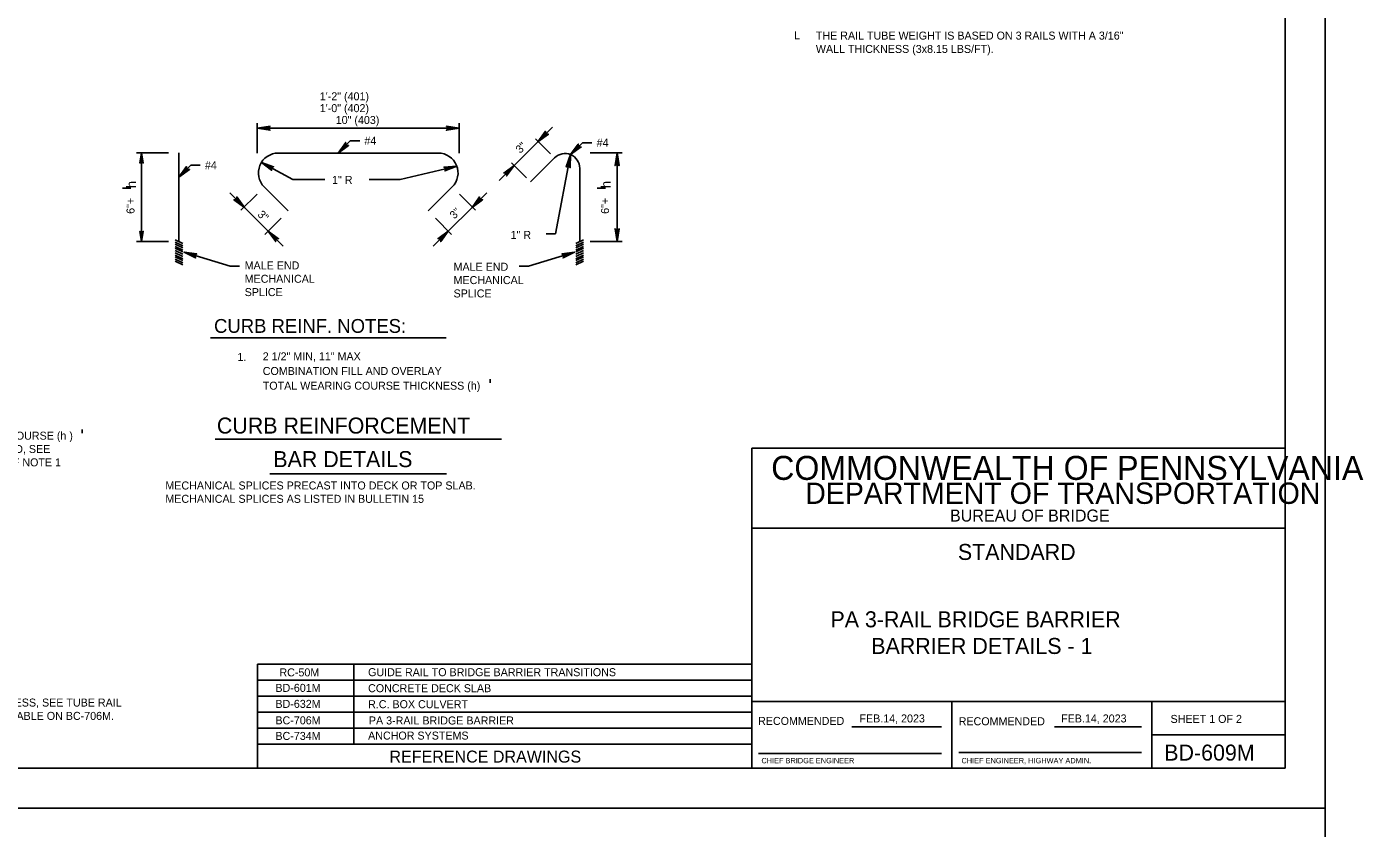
# Model space of a CAD drawing. Extents: x 641054 to 641910, y 298137 to 299325.
# Drawn here: x 641409 to 641910, y 298724 to 299024 of the extents above; entities that cross this region are included whole.
import ezdxf

# ---------------------------------------------------------------- set-up
doc = ezdxf.new("R2010")
doc.units = 0
for name, color, linetype in [('1', 7, 'Continuous'), ('2', 7, 'Continuous'), ('4', 7, 'Continuous'), ('DATES', 7, 'Continuous'), ('PLT-BNDY', 7, 'Continuous'), ('SIGNATORY TITLES', 7, 'Continuous')]:
    doc.layers.add(name, color=color, linetype=linetype)

msp = doc.modelspace()

# ---------------------------------------------------------------- linework, layer by layer
at = {"layer": '1'}
for p, q in [((641467.09, 298939.97), (641464.27, 298941.33)), ((641467.09, 298939.09), (641464.27, 298940.46)), ((641467.09, 298943.18), (641464.28, 298944.55)), ((641467.09, 298942.31), (641464.28, 298943.68)), ((641467.09, 298941.56), (641464.28, 298942.92)), ((641467.09, 298940.68), (641464.28, 298942.04)), ((641614.55, 298943.18), (641617.36, 298944.55)), ((641614.55, 298942.31), (641617.36, 298943.68)), ((641614.55, 298941.56), (641617.36, 298942.92)), ((641614.55, 298940.68), (641617.36, 298942.04)), ((641614.55, 298939.97), (641617.37, 298941.33)), ((641614.55, 298939.09), (641617.37, 298940.46)), ((641467.09, 298938.3), (641464.27, 298939.66)), ((641467.09, 298937.43), (641464.27, 298938.79)), ((641467.09, 298935.84), (641464.27, 298937.21)), ((641467.09, 298936.71), (641464.28, 298938.08)), ((641467.09, 298935.08), (641464.28, 298936.45)), ((641484.85, 298934.68), (641467.59, 298939.85)), ((641596.79, 298934.68), (641614.05, 298939.85)), ((641614.55, 298938.3), (641617.37, 298939.66)), ((641614.55, 298937.43), (641617.37, 298938.79)), ((641614.55, 298936.71), (641617.36, 298938.08)), ((641614.55, 298935.84), (641617.37, 298937.21)), ((641614.55, 298935.08), (641617.36, 298936.45)), ((641582.43, 298890.84), (641582.43, 298892.25))]:
    msp.add_line(p, q, dxfattribs=at)
for points in [[(641499.61, 298985.77), (641499.44, 298986.1), (641495.06, 298986.34), (641499.61, 298985.77), (641499.84, 298985.57), (641495.06, 298986.34), (641499.43, 298986.55), (641499.59, 298986.88), (641495.06, 298986.34), (641499.84, 298987.1), (641499.59, 298986.88)], [(641566.21, 298986.91), (641566.38, 298986.58), (641570.75, 298986.34), (641566.21, 298986.91), (641565.98, 298987.11), (641570.75, 298986.34), (641566.38, 298986.12), (641566.22, 298985.8), (641570.75, 298986.34), (641565.98, 298985.58), (641566.22, 298985.8)], [(641603.9, 298984.1), (641603.55, 298984.21), (641600.29, 298981.29), (641603.9, 298984.1), (641604.21, 298984.12), (641600.29, 298981.29), (641603.22, 298984.53), (641603.11, 298984.87), (641600.29, 298981.29), (641603.13, 298985.2), (641603.11, 298984.87)], [(641630.54, 298972.56), (641630.21, 298972.73), (641629.97, 298977.1), (641630.54, 298972.56), (641630.74, 298972.32), (641629.97, 298977.1), (641629.75, 298972.73), (641629.43, 298972.57), (641629.97, 298977.1), (641629.21, 298972.32), (641629.43, 298972.57)], [(641500.34, 298970.87), (641500.34, 298971.24), (641496.61, 298973.53), (641500.34, 298970.87), (641500.45, 298970.58), (641496.61, 298973.53), (641500.56, 298971.64), (641500.85, 298971.85), (641496.61, 298973.53), (641501.17, 298971.93), (641500.85, 298971.85)], [(641565.33, 298971.66), (641565.57, 298971.38), (641569.88, 298972.15), (641565.33, 298971.66), (641565.06, 298971.8), (641569.88, 298972.15), (641565.68, 298970.94), (641565.6, 298970.58), (641569.88, 298972.15), (641565.41, 298970.32), (641565.6, 298970.58)], [(641587.77, 298969.58), (641588.12, 298969.46), (641591.38, 298972.38), (641587.77, 298969.58), (641587.47, 298969.55), (641591.38, 298972.38), (641588.45, 298969.14), (641588.57, 298968.8), (641591.38, 298972.38), (641588.55, 298968.47), (641588.57, 298968.8)], [(641486.61, 298959.49), (641486.97, 298959.6), (641490.23, 298956.68), (641486.61, 298959.49), (641486.31, 298959.51), (641490.23, 298956.68), (641487.29, 298959.92), (641487.41, 298960.26), (641490.23, 298956.68), (641487.39, 298960.59), (641487.41, 298960.26)], [(641579.2, 298959.49), (641578.85, 298959.6), (641575.59, 298956.68), (641579.2, 298959.49), (641579.51, 298959.51), (641575.59, 298956.68), (641578.52, 298959.92), (641578.41, 298960.26), (641575.59, 298956.68), (641578.43, 298960.59), (641578.41, 298960.26)], [(641502.74, 298944.97), (641502.39, 298944.86), (641499.13, 298947.78), (641502.74, 298944.97), (641503.05, 298944.94), (641499.13, 298947.78), (641502.07, 298944.53), (641501.95, 298944.19), (641499.13, 298947.78), (641501.97, 298943.86), (641501.95, 298944.19)], [(641563.07, 298944.97), (641563.42, 298944.86), (641566.68, 298947.78), (641563.07, 298944.97), (641562.77, 298944.94), (641566.68, 298947.78), (641563.75, 298944.53), (641563.87, 298944.19), (641566.68, 298947.78), (641563.85, 298943.86), (641563.87, 298944.19)], [(641630.54, 298948.4), (641630.21, 298948.23), (641629.97, 298943.86), (641630.54, 298948.4), (641630.74, 298948.64), (641629.97, 298943.86), (641629.75, 298948.23), (641629.43, 298948.39), (641629.97, 298943.86), (641629.21, 298948.64), (641629.43, 298948.39)], [(641472.1, 298939.09), (641471.84, 298938.83), (641467.59, 298939.85), (641472.1, 298939.09), (641472.38, 298939.22), (641467.59, 298939.85), (641471.71, 298938.39), (641471.77, 298938.03), (641467.59, 298939.85), (641471.94, 298937.75), (641471.77, 298938.03)], [(641609.54, 298939.09), (641609.8, 298938.83), (641614.05, 298939.85), (641609.54, 298939.09), (641609.26, 298939.22), (641614.05, 298939.85), (641609.93, 298938.39), (641609.87, 298938.03), (641614.05, 298939.85), (641609.7, 298937.75), (641609.87, 298938.03)]]:
    msp.add_lwpolyline(points, dxfattribs=at)
at = {"layer": '2'}
for p, q in [((641880.49, 299310.38), (641880.49, 298746.38)), ((641495.06, 298977.03), (641495.06, 298988.26)), ((641570.75, 298986.34), (641495.06, 298986.34)), ((641570.75, 298977.03), (641570.75, 298988.26)), ((641600.29, 298981.29), (641605.78, 298986.78)), ((641525.34, 298977.03), (641529.95, 298981.64)), ((641533.46, 298981.64), (641529.95, 298981.64)), ((641591.38, 298972.38), (641600.29, 298981.29)), ((641599.42, 298982.36), (641604.98, 298976.81)), ((641612.55, 298976.44), (641617.04, 298980.93)), ((641620.55, 298980.93), (641617.04, 298980.93)), ((641449.78, 298977.07), (641461.74, 298977.07)), ((641606.9, 298946.8), (641612.55, 298976.44)), ((641631.86, 298977.07), (641619.9, 298977.07)), ((641465.69, 298968), (641470.18, 298972.49)), ((641473.69, 298972.49), (641470.18, 298972.49)), ((641496.61, 298973.53), (641508.43, 298967.14)), ((641548.61, 298967.14), (641569.88, 298972.15)), ((641585.7, 298966.7), (641591.38, 298972.38)), ((641590.41, 298973.36), (641595.97, 298967.8)), ((641520.4, 298967.14), (641508.43, 298967.14)), ((641537.01, 298967.14), (641548.61, 298967.14)), ((641444.52, 298963.9), (641447.67, 298963.9)), ((641490.23, 298956.68), (641484.73, 298962.18)), ((641494.97, 298961.63), (641488.91, 298955.57)), ((641570.84, 298961.63), (641576.9, 298955.57)), ((641575.59, 298956.68), (641581.08, 298962.18)), ((641622.44, 298963.9), (641625.58, 298963.9)), ((641499.13, 298947.78), (641490.23, 298956.68)), ((641566.68, 298947.78), (641575.59, 298956.68)), ((641503.98, 298952.63), (641497.92, 298946.56)), ((641561.83, 298952.63), (641567.9, 298946.56)), ((641504.82, 298942.09), (641499.13, 298947.78)), ((641561, 298942.09), (641566.68, 298947.78)), ((641606.9, 298946.8), (641603.39, 298946.8)), ((641449.78, 298943.86), (641461.74, 298943.86)), ((641631.86, 298943.86), (641619.9, 298943.86)), ((641488.36, 298934.68), (641484.85, 298934.68)), ((641596.79, 298934.68), (641593.28, 298934.68)), ((641477.54, 298907.79), (641565.84, 298907.79)), ((641429.35, 298871.98), (641429.35, 298873.37)), ((641479.24, 298869.79), (641586.58, 298869.79)), ((641880.49, 298866.38), (641680.49, 298866.38)), ((641680.49, 298866.38), (641680.49, 298746.38)), ((641880.49, 298746.38), (641880.49, 298866.38)), ((641499.81, 298856.78), (641566.01, 298856.78)), ((641880.49, 298836.38), (641680.49, 298836.38)), ((641495.11, 298785.38), (641495.11, 298746.38)), ((641495.11, 298785.38), (641680.49, 298785.38)), ((641531.24, 298785.38), (641531.24, 298755.38)), ((641495.11, 298779.38), (641680.49, 298779.38)), ((641495.11, 298773.38), (641680.49, 298773.38)), ((641880.49, 298771.38), (641680.49, 298771.38)), ((641755.49, 298746.38), (641755.49, 298771.38)), ((641830.49, 298771.38), (641830.49, 298746.38)), ((641495.11, 298767.38), (641680.49, 298767.38)), ((641495.11, 298761.38), (641680.49, 298761.38)), ((641717.94, 298761.88), (641751.63, 298761.88)), ((641793.93, 298761.88), (641826.54, 298761.88)), ((641495.11, 298755.38), (641680.49, 298755.38)), ((641830.49, 298758.88), (641880.49, 298758.88)), ((641682.99, 298751.88), (641751.63, 298751.88)), ((641758.11, 298752.25), (641826.54, 298752.25)), ((641094.49, 298746.38), (641880.49, 298746.38))]:
    msp.add_line(p, q, dxfattribs=at)
for points in [[(641529.01, 298979.89), (641528.65, 298980), (641525.34, 298977.03), (641529.01, 298979.89), (641529.32, 298979.91), (641525.34, 298977.03), (641528.32, 298980.33), (641528.2, 298980.67), (641525.34, 298977.03), (641528.22, 298981.01), (641528.2, 298980.67)], [(641616.22, 298979.29), (641615.86, 298979.41), (641612.55, 298976.44), (641616.22, 298979.29), (641616.53, 298979.32), (641612.55, 298976.44), (641615.53, 298979.73), (641615.41, 298980.08), (641612.55, 298976.44), (641615.43, 298980.41), (641615.41, 298980.08)], [(641451.21, 298973.46), (641451.48, 298973.6), (641451.67, 298977.1), (641451.21, 298973.46), (641451.05, 298973.28), (641451.67, 298977.1), (641451.84, 298973.6), (641452.1, 298973.47), (641451.67, 298977.1), (641452.28, 298973.28), (641452.1, 298973.47)], [(641451.67, 298943.86), (641451.67, 298977.07)], [(641611.12, 298972.02), (641611.48, 298972.12), (641612.55, 298976.44), (641611.12, 298972.02), (641610.88, 298971.82), (641612.55, 298976.44), (641611.94, 298972.04), (641612.23, 298971.82), (641612.55, 298976.44), (641612.4, 298971.53), (641612.23, 298971.82)], [(641629.97, 298943.86), (641629.97, 298977.07)], [(641469.36, 298970.85), (641469, 298970.97), (641465.69, 298968), (641469.36, 298970.85), (641469.67, 298970.88), (641465.69, 298968), (641468.67, 298971.29), (641468.55, 298971.64), (641465.69, 298968), (641468.57, 298971.97), (641468.55, 298971.64)], [(641451.21, 298947.5), (641451.48, 298947.36), (641451.67, 298943.86), (641451.21, 298947.5), (641451.05, 298947.68), (641451.67, 298943.86), (641451.84, 298947.36), (641452.1, 298947.49), (641451.67, 298943.86), (641452.28, 298947.68), (641452.1, 298947.49)]]:
    msp.add_lwpolyline(points, dxfattribs=at)
at = {"layer": '4'}
for p, q in [((641465.69, 298977.07), (641465.69, 298943.86)), ((641562.89, 298977.03), (641502.93, 298977.03)), ((641597.53, 298966.24), (641606.54, 298975.24)), ((641615.95, 298971.35), (641615.95, 298943.86)), ((641506.67, 298955.32), (641497.66, 298964.32)), ((641559.14, 298955.32), (641568.15, 298964.32))]:
    msp.add_line(p, q, dxfattribs=at)
for centre, radius, start, end in [((641502.93, 298969.59), 7.44, 90, 225), ((641562.89, 298969.59), 7.44, 315, 90), ((641610.44, 298971.35), 5.51, 360, 135)]:
    msp.add_arc(centre, radius, start, end, dxfattribs=at)
at = {"layer": 'PLT-BNDY'}
for points in [[(641054.49, 299325.38), (641895.49, 299325.38), (641895.49, 298731.38), (641054.49, 298731.38)], [(641054.49, 298731.38), (641895.49, 298731.38), (641895.49, 298137.38), (641054.49, 298137.38)]]:
    msp.add_lwpolyline(points, close=True, dxfattribs=at)

# ---------------------------------------------------------------- texts
at = {"layer": '1'}
msp.add_text('1.', height=3, dxfattribs=at).set_placement((641487.63, 298899.12))
at = {"layer": '2'}
for s, height, p in [('L', 3, (641696.36, 299019.67)), ('THE RAIL TUBE WEIGHT IS BASED ON 3 RAILS WITH A 3/16" ', 3, (641704.49, 299019.58)), ('WALL THICKNESS (3x8.15 LBS/FT).', 3, (641704.49, 299014.58)), ('1\'-2" (401)', 2.9997, (641518.48, 298996.82)), ('1\'-0" (402)', 2.9997, (641518.48, 298992.38)), ('10" (403)', 3, (641524.48, 298987.94)), ('#4', 3, (641535.21, 298980.15)), ('#4', 3, (641622.3, 298979.44)), ('#4', 3, (641475.44, 298971)), ('1" R', 3, (641523.09, 298965.49)), ('1" R', 3, (641590.03, 298944.86)), ('MALE END', 3, (641490.33, 298933.41)), ('MALE END', 3, (641568.65, 298932.91)), ('MECHANICAL', 3, (641490.33, 298928.41)), ('MECHANICAL', 3, (641568.65, 298927.91)), ('SPLICE', 3, (641490.33, 298923.41)), ('SPLICE', 3, (641568.65, 298922.91)), ('CURB REINF. NOTES:', 5.1839, (641478.85, 298909.63)), ('2 1/2" MIN, 11" MAX', 3, (641497.11, 298899.32)), ('COMBINATION FILL AND OVERLAY', 3, (641497.11, 298893.82)), ('TOTAL WEARING COURSE THICKNESS (h)', 3, (641497.11, 298888.32)), ('CURB REINFORCEMENT', 6, (641479.92, 298871.87)), ('WEARING COURSE (h )', 3.0001, (641381.35, 298869.57)), ('IF REQUIRED, SEE', 3.0001, (641381.35, 298864.57)), ('BAR DETAILS', 6, (641501.07, 298859.29)), ('CURB REINF NOTE 1', 3.0001, (641381.35, 298859.57)), ('COMMONWEALTH OF PENNSYLVANIA', 9, (641687.74, 298854.5)), ('MECHANICAL SPLICES PRECAST INTO DECK OR TOP SLAB.', 3, (641460.6, 298850.9)), ('DEPARTMENT OF TRANSPORTATION', 8.0002, (641700.49, 298845.5)), ('MECHANICAL SPLICES AS LISTED IN BULLETIN 15', 3, (641460.6, 298845.9)), ('BUREAU OF BRIDGE', 4.5, (641754.79, 298838.88)), ('STANDARD', 6, (641757.74, 298824.48)), ('PA 3-RAIL BRIDGE BARRIER', 6, (641709.96, 298799.23)), ('BARRIER DETAILS - 1', 6, (641725.27, 298789.23)), ('RC-50M', 3, (641503.36, 298780.83)), ('GUIDE RAIL TO BRIDGE BARRIER TRANSITIONS', 3, (641536.61, 298780.9)), ('BD-601M', 3, (641501.86, 298775.02)), ('CONCRETE DECK SLAB', 3, (641536.61, 298774.9)), ('FOR TUBE THICKNESS, SEE TUBE RAIL', 3, (641367.77, 298769.51)), ('BD-632M', 3, (641501.86, 298769.02)), ('R.C. BOX CULVERT', 3, (641536.61, 298768.9)), ('SPECIFICATIONS TABLE ON BC-706M.', 3, (641367.77, 298764.51)), ('BC-706M', 3, (641501.86, 298762.85)), ('PA 3-RAIL BRIDGE BARRIER', 3, (641536.9, 298762.79)), ('SHEET 1 OF 2', 3, (641837.47, 298763.38)), ('BC-734M', 3, (641501.86, 298757)), ('ANCHOR SYSTEMS', 3, (641536.61, 298757.13)), ('BD-609M', 6, (641835.11, 298749.25)), ('REFERENCE DRAWINGS', 4.5, (641544.61, 298748.5))]:
    msp.add_text(s, height=height, dxfattribs=at).set_placement(p)
for s, height, rotation, p in [('3"', 3, 45, (641593.68, 298976.72)), ('h', 3.6, 90, (641449.63, 298963.9)), ('h', 3.6, 90, (641627.54, 298963.9)), ('6"+  ', 3, 90, (641449.04, 298954.25)), ('3"', 3, 315, (641494.94, 298953.75)), ('3"', 3, 45, (641568.98, 298952.11)), ('6"+  ', 3, 90, (641626.95, 298954.25)), ('RECOMMENDED', 3, 360, (641682.82, 298762.63)), ('RECOMMENDED', 3, 360, (641758.04, 298762.5))]:
    msp.add_text(s, height=height, rotation=rotation, dxfattribs=at).set_placement(p)
at = {"layer": 'DATES'}
for p in [(641720.83, 298763.56), (641796.44, 298763.56)]:
    msp.add_text('FEB.14, 2023', height=3, dxfattribs=at).set_placement(p)
at = {"layer": 'SIGNATORY TITLES'}
for s, p in [('CHIEF BRIDGE ENGINEER', (641684.08, 298748.25)), ('CHIEF ENGINEER, HIGHWAY ADMIN.', (641759.08, 298748.25))]:
    msp.add_text(s, height=2, dxfattribs=at).set_placement(p)

doc.saveas('drawing.dxf')
